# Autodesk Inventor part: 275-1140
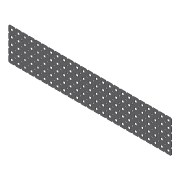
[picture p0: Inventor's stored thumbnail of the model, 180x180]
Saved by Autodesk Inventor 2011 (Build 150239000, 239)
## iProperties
Company: Autodesk Inc.
Created: 2005-08
Part Number: 275-1140
Document SubType Name: Sheet Metal
Designer: Autodesk Inc.
Density: 1 g/cm^3
Sheet Metal Rule: Default
Catalog Web Link: http://www.vexrobotics.com/products/accessories/structure/plate.html
Description: Plate with holes on 0.500" increments and 1/8" diamonds in between. Can be cut on 0.500" increments.
Vendor: Innovation First, Inc.
Author: Autodesk Inc.
Title: VEX Robotics Kit of Parts
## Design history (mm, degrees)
node "Face1"
  sketch "Sketch1"
    geometry: L1 (-15.07, 9.738)-(-23.96, 9.738); L2 (-25.865, 7.833)-(-25.865, -1.057); L3 (-23.96, -2.962)-(-15.07, -2.962); L4 (-13.165, -1.057)-(-13.165, 7.833); L5 (-25.865, 7.833)-(-23.96, 9.738); L6 (-25.865, -1.057)-(-23.96, -2.962); L7 (-15.07, -2.962)-(-13.165, -1.057); L8 (-13.165, 7.833)-(-15.07, 9.738); L9 (-21.801, 5.674)-(-17.229, 5.674); L10 (-17.229, 5.674)-(-17.229, 1.102); L11 (-17.229, 1.102)-(-21.801, 1.102); L12 (-21.801, 1.102)-(-21.801, 5.674); 4 further points
    constraints: 24 end point, 8 point on line, 4 parallel, 2 horizontal, 2 perpendicular
    dimensions: "d0" = 12.7 distance of point (-25.865, 9.738) point (-25.865, -2.962); "d1" = 12.7 distance of point (-13.165, 9.738) point (-25.865, 9.738); "d2" = 1.905 distance of L2.start point (-25.865, 9.738); "d3" = 1.905 distance of L1.end point (-25.865, 9.738) (= d2); "d4" = 1.905 distance of L2.end point (-25.865, -2.962) (= d2); "d5" = 1.905 distance of L3.start point (-25.865, -2.962) (= d4); "d6" = 1.905 distance of L3.end point (-13.165, -2.962) (= d2); "d7" = 1.905 distance of L4.start point (-13.165, -2.962) (= d6); "d8" = 1.905 distance of L4.end point (-13.165, 9.738) (= d2); "d9" = 1.905 distance of L1.start point (-13.165, 9.738) (= d8); "d10" = 4.572 distance of L11.end L9.start; "d11" = 4.572 distance of L10.end L11.end; "d12" = 4.064 distance between parallel lines of L1 L9; "d13" = 4.064 distance between parallel lines of L4 L10
body "Solid1"
pattern_linear "Rectangular Pattern1" dims "d17" = 12.7, "d23" = 12.7
face "Plate1" dims "Thickness" = 0.8509
other parameters: "BendRadius" = 0.8509 (= Thickness), "BendReliefWidth" = 0.8509 (= Thickness), "BendReliefDepth" = 0.42545 (= 0.5 x Thickness), "CornerReliefSize" = 3.4036 (= 4 x Thickness), "SeamGap" = 0.00508, "MinimumRemnant" = 1.7018 (= 2 x Thickness), "TransitionRadius" = 0.8509 (= BendRadius), "d14" = 0.8509 (= BendRadius), "JacobiRadiusSize" = 0.8509 (= Thickness), "GapSize" = 0.8509 (= Thickness)
